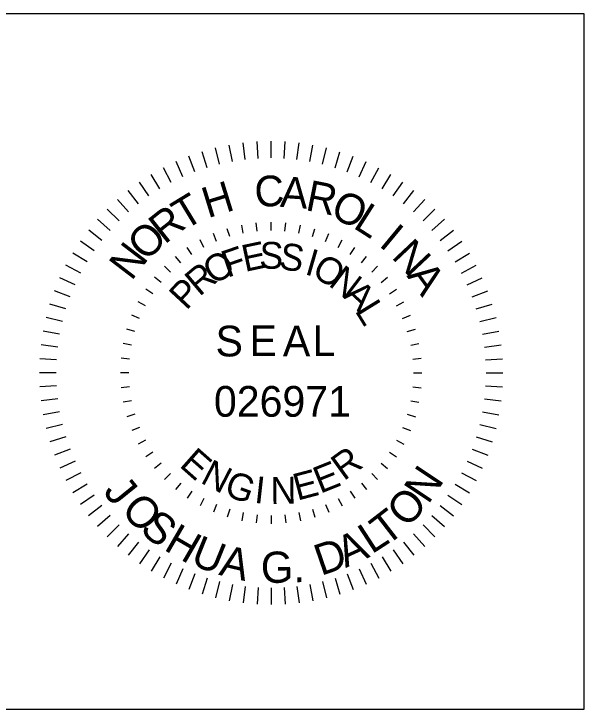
# Model space of a CAD drawing. Extents: x 1882804 to 1884487, y 844572 to 845443.
# Drawn here: x 1884277.3 to 1884369.6, y 845330.9 to 845443.4 of the extents above; entities that cross this region are included whole.
import ezdxf

# ---------------------------------------------------------------- set-up
doc = ezdxf.new("R2010")
doc.units = 0
doc.layers.add('Scratch_Level_1', color=7, linetype='Continuous')
doc.layers.add('Sheet Title CELL', color=7, linetype='Continuous')

msp = doc.modelspace()

# ---------------------------------------------------------------- linework, layer by layer
at = {"layer": 'Scratch_Level_1'}
msp.add_lwpolyline([(1884269.6, 845330.93), (1884369.6, 845330.93), (1884369.6, 845443.43), (1884269.6, 845443.43)], close=True, dxfattribs=at)
at = {"layer": 'Sheet Title CELL'}
for p, q in [((1884312.67, 845419.55), (1884312.18, 845422.21)), ((1884314.74, 845419.86), (1884314.42, 845422.55)), ((1884316.84, 845420.05), (1884316.67, 845422.76)), ((1884318.94, 845420.12), (1884318.94, 845422.83)), ((1884321.04, 845420.05), (1884321.2, 845422.76)), ((1884323.13, 845419.86), (1884323.46, 845422.55)), ((1884325.21, 845419.55), (1884325.7, 845422.21)), ((1884308.59, 845418.54), (1884307.78, 845421.13)), ((1884310.61, 845419.1), (1884309.96, 845421.74)), ((1884327.26, 845419.1), (1884327.91, 845421.74)), ((1884329.29, 845418.54), (1884330.09, 845421.13)), ((1884304.66, 845417.05), (1884303.55, 845419.52)), ((1884306.6, 845417.85), (1884305.64, 845420.39)), ((1884331.27, 845417.85), (1884332.23, 845420.39)), ((1884333.22, 845417.05), (1884334.33, 845419.52)), ((1884302.77, 845416.13), (1884301.51, 845418.53)), ((1884335.1, 845416.13), (1884336.36, 845418.53)), ((1884300.94, 845415.1), (1884299.54, 845417.42)), ((1884336.93, 845415.1), (1884338.34, 845417.42)), ((1884299.17, 845413.96), (1884297.63, 845416.19)), ((1884338.7, 845413.96), (1884340.24, 845416.19)), ((1884297.48, 845412.71), (1884295.81, 845414.84)), ((1884340.39, 845412.71), (1884342.06, 845414.84)), ((1884295.87, 845411.37), (1884294.07, 845413.4)), ((1884342.01, 845411.37), (1884343.8, 845413.4)), ((1884294.34, 845409.93), (1884292.42, 845411.84)), ((1884343.54, 845409.93), (1884345.45, 845411.84)), ((1884292.9, 845408.39), (1884290.87, 845410.19)), ((1884316.68, 845408.26), (1884316.55, 845409.61)), ((1884318.94, 845408.37), (1884318.94, 845409.72)), ((1884321.19, 845408.26), (1884321.33, 845409.61)), ((1884344.98, 845408.39), (1884347.01, 845410.19)), ((1884291.55, 845406.78), (1884289.42, 845408.45)), ((1884312.25, 845407.38), (1884311.85, 845408.67)), ((1884314.44, 845407.93), (1884314.18, 845409.26)), ((1884323.43, 845407.93), (1884323.7, 845409.26)), ((1884325.62, 845407.38), (1884326.02, 845408.67)), ((1884346.32, 845406.78), (1884348.46, 845408.45)), ((1884310.12, 845406.61), (1884309.6, 845407.87)), ((1884327.75, 845406.61), (1884328.27, 845407.87)), ((1884290.31, 845405.09), (1884288.08, 845406.63)), ((1884308.07, 845405.65), (1884307.44, 845406.84)), ((1884329.8, 845405.65), (1884330.44, 845406.84)), ((1884347.57, 845405.09), (1884349.8, 845406.63)), ((1884306.13, 845404.49), (1884305.38, 845405.61)), ((1884331.74, 845404.49), (1884332.49, 845405.61)), ((1884289.16, 845403.32), (1884286.84, 845404.73)), ((1884304.32, 845403.14), (1884303.46, 845404.18)), ((1884333.55, 845403.14), (1884334.41, 845404.18)), ((1884348.71, 845403.32), (1884351.03, 845404.73)), ((1884288.13, 845401.49), (1884285.73, 845402.75)), ((1884349.74, 845401.49), (1884352.14, 845402.75)), ((1884302.64, 845401.62), (1884301.69, 845402.58)), ((1884335.23, 845401.62), (1884336.19, 845402.58)), ((1884287.21, 845399.6), (1884284.74, 845400.72)), ((1884301.13, 845399.94), (1884300.08, 845400.8)), ((1884336.75, 845399.94), (1884337.8, 845400.8)), ((1884350.66, 845399.6), (1884353.13, 845400.72)), ((1884286.41, 845397.66), (1884283.87, 845398.62)), ((1884299.78, 845398.13), (1884298.65, 845398.88)), ((1884338.1, 845398.13), (1884339.22, 845398.88)), ((1884351.46, 845397.66), (1884354, 845398.62)), ((1884285.72, 845395.68), (1884283.14, 845396.48)), ((1884298.61, 845396.19), (1884297.42, 845396.83)), ((1884339.26, 845396.19), (1884340.45, 845396.83)), ((1884352.15, 845395.68), (1884354.74, 845396.48)), ((1884285.16, 845393.65), (1884282.53, 845394.3)), ((1884297.65, 845394.14), (1884296.4, 845394.66)), ((1884340.23, 845394.14), (1884341.48, 845394.66)), ((1884352.71, 845393.65), (1884355.35, 845394.3)), ((1884284.72, 845391.6), (1884282.05, 845392.08)), ((1884296.89, 845392.01), (1884295.59, 845392.41)), ((1884340.99, 845392.01), (1884342.29, 845392.41)), ((1884353.16, 845391.6), (1884355.82, 845392.08)), ((1884284.4, 845389.52), (1884281.71, 845389.85)), ((1884296.34, 845389.82), (1884295.01, 845390.08)), ((1884341.54, 845389.82), (1884342.87, 845390.08)), ((1884353.47, 845389.52), (1884356.16, 845389.85)), ((1884284.21, 845387.42), (1884281.5, 845387.59)), ((1884296, 845387.58), (1884294.66, 845387.72)), ((1884341.87, 845387.58), (1884343.22, 845387.72)), ((1884353.66, 845387.42), (1884356.37, 845387.59)), ((1884284.15, 845385.33), (1884281.44, 845385.33)), ((1884295.89, 845385.33), (1884294.54, 845385.33)), ((1884341.98, 845385.33), (1884343.33, 845385.33)), ((1884353.73, 845385.33), (1884356.44, 845385.33)), ((1884284.21, 845383.22), (1884281.5, 845383.06)), ((1884296, 845383.07), (1884294.66, 845382.94)), ((1884341.87, 845383.07), (1884343.22, 845382.94)), ((1884353.66, 845383.22), (1884356.37, 845383.06)), ((1884284.4, 845381.13), (1884281.71, 845380.81)), ((1884296.34, 845380.83), (1884295.01, 845380.57)), ((1884341.54, 845380.83), (1884342.87, 845380.57)), ((1884353.47, 845381.13), (1884356.16, 845380.81)), ((1884284.72, 845379.05), (1884282.05, 845378.57)), ((1884353.16, 845379.05), (1884355.82, 845378.57)), ((1884296.89, 845378.64), (1884295.59, 845378.24)), ((1884340.99, 845378.64), (1884342.29, 845378.24)), ((1884285.16, 845377), (1884282.53, 845376.35)), ((1884352.71, 845377), (1884355.35, 845376.35)), ((1884297.65, 845376.51), (1884296.4, 845375.99)), ((1884340.23, 845376.51), (1884341.48, 845375.99)), ((1884285.72, 845374.98), (1884283.14, 845374.17)), ((1884352.15, 845374.97), (1884354.74, 845374.17)), ((1884298.61, 845374.46), (1884297.42, 845373.82)), ((1884339.26, 845374.46), (1884340.45, 845373.82)), ((1884286.41, 845372.99), (1884283.87, 845372.03)), ((1884299.78, 845372.52), (1884298.65, 845371.77)), ((1884338.1, 845372.52), (1884339.22, 845371.77)), ((1884351.46, 845372.99), (1884354, 845372.03)), ((1884287.21, 845371.05), (1884284.74, 845369.93)), ((1884301.13, 845370.71), (1884300.08, 845369.85)), ((1884336.75, 845370.71), (1884337.8, 845369.85)), ((1884350.66, 845371.05), (1884353.13, 845369.93)), ((1884288.13, 845369.16), (1884285.73, 845367.9)), ((1884302.64, 845369.03), (1884301.69, 845368.07)), ((1884335.23, 845369.03), (1884336.19, 845368.07)), ((1884349.74, 845369.16), (1884352.14, 845367.9)), ((1884289.16, 845367.33), (1884286.84, 845365.92)), ((1884304.32, 845367.51), (1884303.46, 845366.46)), ((1884333.55, 845367.51), (1884334.41, 845366.46)), ((1884348.71, 845367.33), (1884351.03, 845365.92)), ((1884290.31, 845365.56), (1884288.08, 845364.02)), ((1884306.13, 845366.17), (1884305.38, 845365.04)), ((1884331.74, 845366.17), (1884332.49, 845365.04)), ((1884347.57, 845365.56), (1884349.8, 845364.02)), ((1884308.07, 845365), (1884307.44, 845363.81)), ((1884329.8, 845365), (1884330.44, 845363.81)), ((1884291.55, 845363.87), (1884289.41, 845362.2)), ((1884310.12, 845364.04), (1884309.6, 845362.78)), ((1884312.25, 845363.27), (1884311.85, 845361.98)), ((1884325.62, 845363.27), (1884326.02, 845361.98)), ((1884327.75, 845364.04), (1884328.27, 845362.78)), ((1884346.32, 845363.87), (1884348.46, 845362.2)), ((1884292.9, 845362.26), (1884290.87, 845360.46)), ((1884314.44, 845362.73), (1884314.18, 845361.4)), ((1884316.68, 845362.39), (1884316.55, 845361.05)), ((1884318.94, 845362.28), (1884318.94, 845360.93)), ((1884321.19, 845362.39), (1884321.33, 845361.05)), ((1884323.43, 845362.73), (1884323.7, 845361.4)), ((1884344.98, 845362.26), (1884347.01, 845360.46)), ((1884294.34, 845360.73), (1884292.42, 845358.81)), ((1884343.54, 845360.73), (1884345.45, 845358.81)), ((1884295.87, 845359.29), (1884294.07, 845357.26)), ((1884342.01, 845359.29), (1884343.8, 845357.26)), ((1884297.48, 845357.94), (1884295.81, 845355.81)), ((1884340.39, 845357.94), (1884342.06, 845355.81)), ((1884299.18, 845356.69), (1884297.63, 845354.46)), ((1884338.7, 845356.69), (1884340.24, 845354.46)), ((1884300.94, 845355.55), (1884299.54, 845353.23)), ((1884336.93, 845355.55), (1884338.34, 845353.23)), ((1884302.77, 845354.52), (1884301.51, 845352.12)), ((1884335.1, 845354.52), (1884336.36, 845352.12)), ((1884304.66, 845353.6), (1884303.55, 845351.13)), ((1884333.22, 845353.6), (1884334.33, 845351.13)), ((1884306.6, 845352.8), (1884305.64, 845350.26)), ((1884308.59, 845352.11), (1884307.78, 845349.52)), ((1884329.29, 845352.11), (1884330.09, 845349.52)), ((1884331.27, 845352.8), (1884332.24, 845350.26)), ((1884310.61, 845351.55), (1884309.96, 845348.92)), ((1884312.67, 845351.11), (1884312.18, 845348.44)), ((1884325.21, 845351.11), (1884325.7, 845348.44)), ((1884327.26, 845351.55), (1884327.91, 845348.92)), ((1884314.74, 845350.79), (1884314.42, 845348.1)), ((1884316.84, 845350.6), (1884316.67, 845347.89)), ((1884318.94, 845350.54), (1884318.94, 845347.83)), ((1884321.04, 845350.6), (1884321.2, 845347.89)), ((1884323.13, 845350.79), (1884323.46, 845348.1))]:
    msp.add_line(p, q, dxfattribs=at)

# ---------------------------------------------------------------- texts
for s, height, rotation, p in [('C', 4.97, 2.9639, (1884316.38, 845412.16)), ('H', 4.97, 17.1424, (1884308.69, 845410.34)), ('A', 4.97, 355.8747, (1884320.32, 845412.22)), ('R', 4.97, 348.7854, (1884324.35, 845411.7)), ('T', 4.97, 31.3208, (1884304.91, 845408.31)), ('O', 4.97, 334.607, (1884328.3, 845410.69)), ('L', 4.97, 327.5178, (1884332.05, 845408.9)), ('R', 4.97, 38.4101, (1884301.7, 845406.03)), ('O', 4.97, 45.4993, (1884298.76, 845403.22)), ('I', 4.97, 320.4285, (1884336.23, 845405.97)), ('N', 4.97, 52.5885, (1884296.34, 845400.1)), ('E', 4.34, 11.9657, (1884314.71, 845401.66)), ('S', 4.34, 357.9015, (1884316.98, 845402.26)), ('S', 4.34, 350.8693, (1884320.07, 845402.21)), ('N', 4.97, 313.3393, (1884338.29, 845404.05)), ('F', 4.34, 18.9978, (1884311.85, 845400.71)), ('I', 4.34, 343.8372, (1884324.23, 845401.34)), ('O', 4.34, 33.0621, (1884309.72, 845399.44)), ('O', 4.34, 329.773, (1884325.33, 845401.11)), ('R', 4.34, 40.0942, (1884307.33, 845397.59)), ('N', 4.34, 322.7408, (1884328.07, 845399.55)), ('A', 4.97, 306.2501, (1884340.81, 845401.03)), ('P', 4.34, 47.1263, (1884305.23, 845395.33)), ('A', 4.34, 315.7087, (1884330.42, 845397.67)), ('L', 4.34, 301.6445, (1884332.41, 845395.4)), ('S', 4.97, 359.9999, (1884309.95, 845388)), ('E', 4.97, 359.9999, (1884315.45, 845388.05)), ('A', 4.97, 359.9999, (1884320.85, 845388.03)), ('L', 4.97, 359.9999, (1884325.66, 845388.05)), ('026971', 4.97, 359.9999, (1884309.69, 845378.24)), ('E', 4.34, 318.5439, (1884303.94, 845370.27)), ('R', 4.34, 35.8972, (1884330.71, 845367.77)), ('N', 4.34, 332.6081, (1884307.34, 845367.63)), ('E', 4.34, 21.8329, (1884326.89, 845365.75)), ('N', 5.05, 56.3346, (1884344.37, 845363.93)), ('G', 4.34, 339.6402, (1884311.14, 845365.62)), ('E', 4.34, 14.8008, (1884323.18, 845364.64)), ('J', 5.05, 308.9576, (1884291.63, 845366.05)), ('I', 4.34, 353.7045, (1884316.12, 845364.32)), ('N', 4.34, 0.7366, (1884318.86, 845364.13)), ('O', 5.05, 47.942, (1884340.97, 845360.08)), ('O', 5.05, 314.4018, (1884294.47, 845362.89)), ('T', 5.05, 37.7051, (1884337.54, 845357.17)), ('S', 5.05, 320.4483, (1884297.52, 845359.71)), ('H', 5.05, 329.8701, (1884301.41, 845356.78)), ('L', 5.05, 33.0156, (1884335.23, 845355.93)), ('U', 5.05, 338.0286, (1884305.69, 845354.46)), ('A', 5.05, 24.4854, (1884330.99, 845353.73)), ('D', 5.05, 18.9594, (1884327.01, 845352.46)), ('A', 5.05, 346.7196, (1884310.35, 845352.67)), ('G.', 5.048, 1.6341, (1884317.35, 845351.29))]:
    msp.add_text(s, height=height, rotation=rotation, dxfattribs=at).set_placement(p)

doc.saveas('drawing.dxf')
